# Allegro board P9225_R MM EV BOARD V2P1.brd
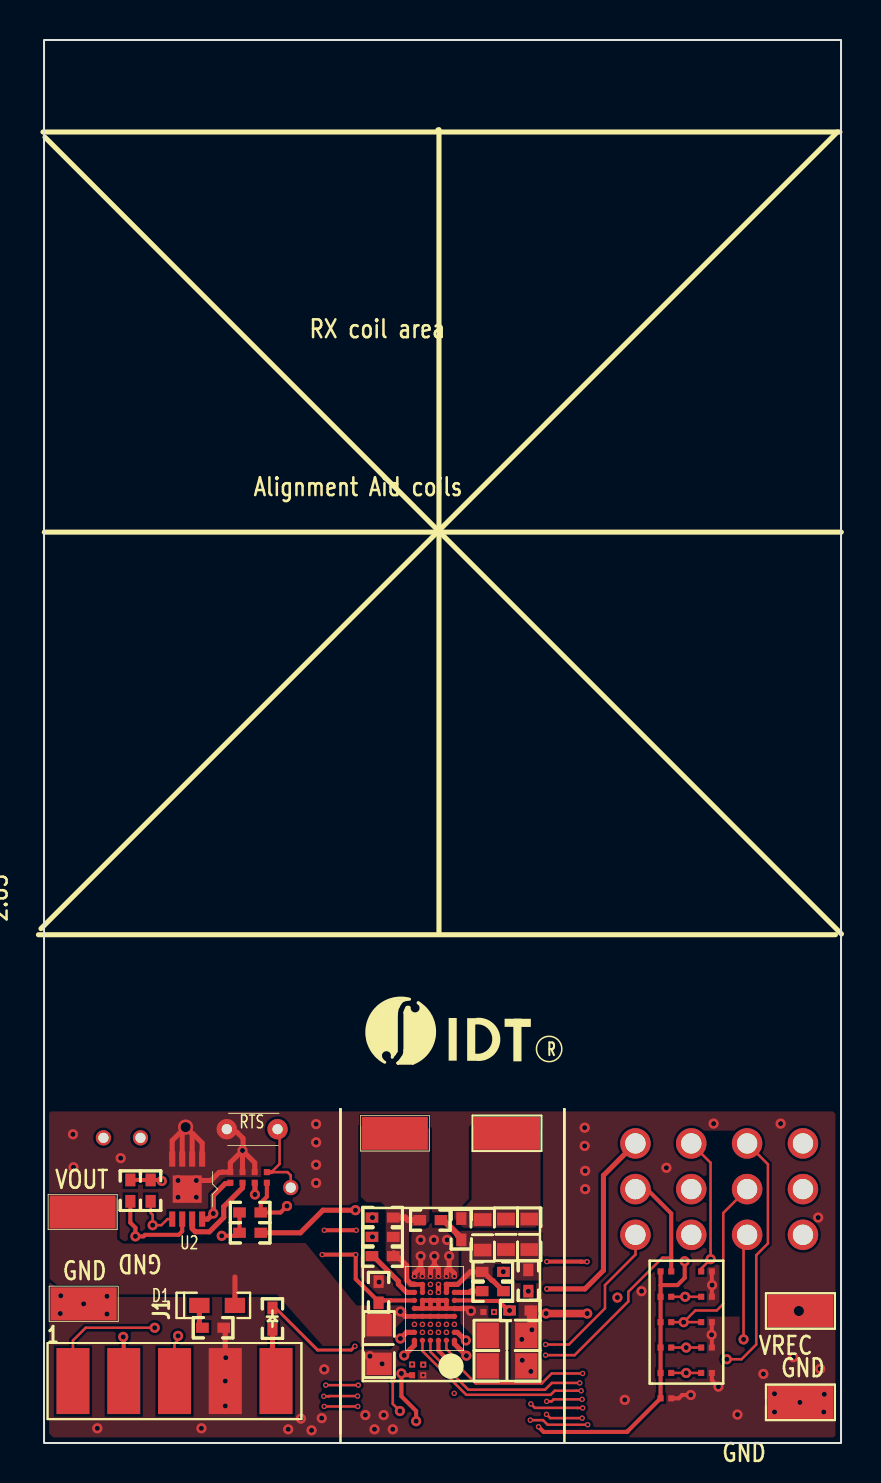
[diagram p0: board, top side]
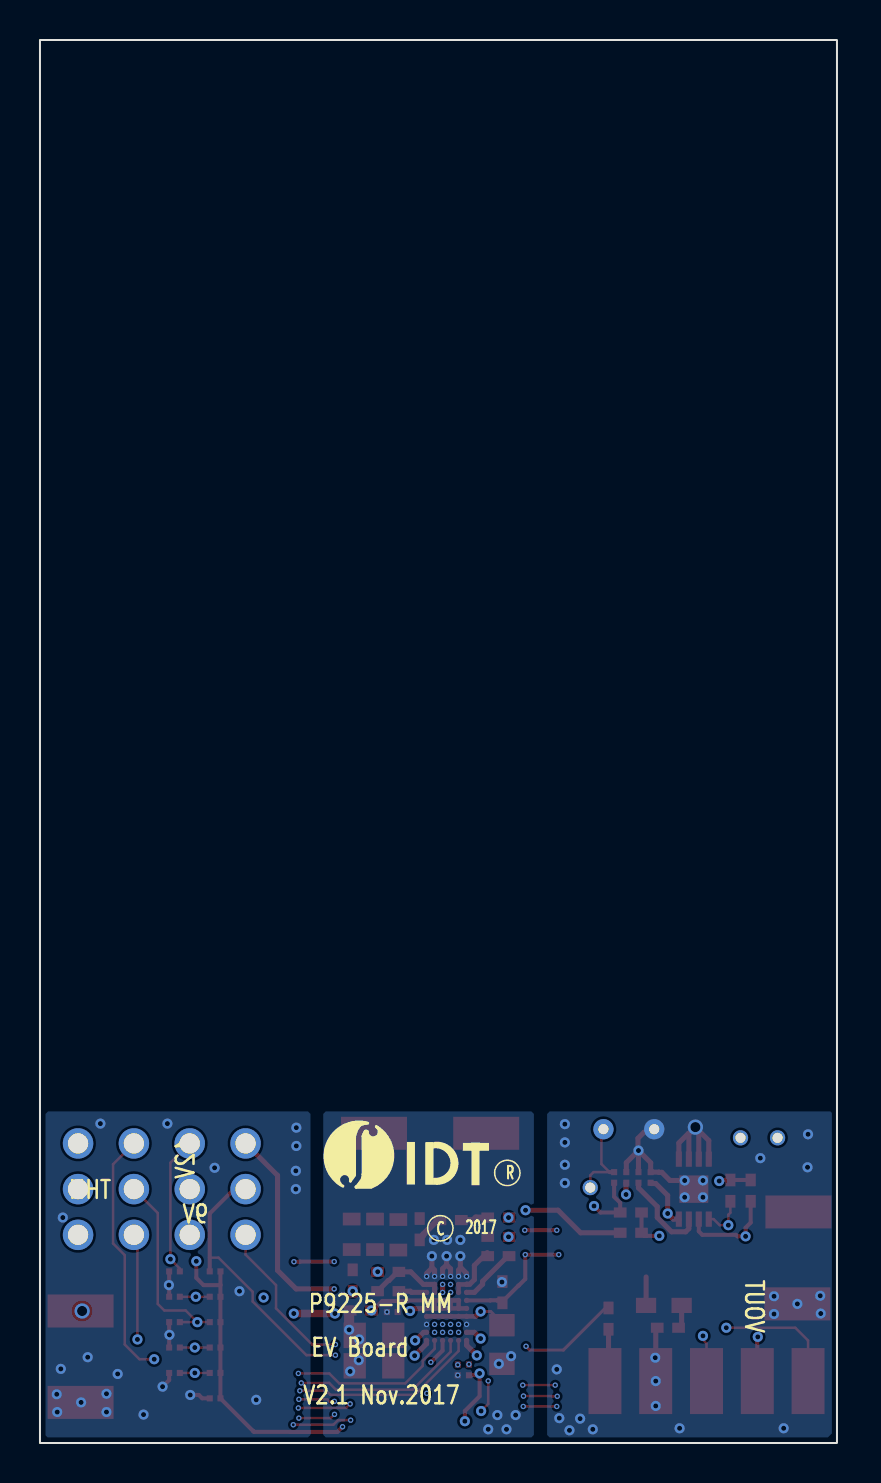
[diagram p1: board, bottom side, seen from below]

Outline 39.88 x 70.18 mm; copper layers: TOP, LAYER_2, LAYER_3, BOTTOM. Coordinates in mm from the lower left corner of the outline.
Outline path: rectangle 0,0 39.88,70.18

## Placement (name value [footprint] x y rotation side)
AC2  NP  [TEST_PT_SM_135X70]  17.55 15.49 0 top
C1  220nF/50V  [0603]  24.28 10.44 90 top
C2  220nF/50V  [0603]  21.95 10.41 90 top
C3  220nF/50V  [0603]  23.11 10.44 90 top
C5  47nF/50V  [0402]  20.88 10.69 90 top
C6  47nF  [0402]  24.23 8.13 270 top
C7  47nF  [0402]  22.45 8.56 0 top
C8  15nF  [0402]  22.45 7.59 180 top
C9  3.3nF  [0402]  19.33 11.15 180 top
C10  22uF  [0805]  16.76 4.93 270 top
C14  47nF  [0402]  16.94 10.31 180 top
C15  47nF  [0402]  16.94 11.28 180 top
C16  15nF  [0402]  16.94 9.35 180 top
C18  1uF  [0402]  23.83 6.63 0 top
C19  0.1uF  [0201]  31.11 2.24 0 top
C20  1uF  [0402]  16.74 7.54 90 top
C21  22uF  [0805]  23.16 5.38 0 top
C22  22uF  [0805]  23.16 3.86 0 top
C23  0.1uF  [0201]  22.25 6.55 0 top
C25  0.1uF  [0201]  9.32 13.28 90 top
C31  0.1uF  [0201]  10.54 13.28 90 top
D1  LED  [0603_DIODE]  8.66 6.88 180 top
D8  1N4148W  [0402]  11.43 6.22 90 top
EOC  PTH_TP  [40MIL_60PAD]  32.38 14.99 0 top
GND  Test Point  [TEST_PT_SM_135X70]  37.85 2.03 0 top
GND1  Test Point  [TEST_PT_SM_135X70]  1.98 6.96 0 top
ILIM  PTH_TP  [40MIL_60PAD]  37.97 10.41 0 top
INT  PTH_TP  [40MIL_60PAD]  29.59 12.7 0 top
J1  I2C  [HEADER_1X5_0P1PITCH60P42D]  6.53 3.1 90 top
LC  NP  [TEST_PT_SM_135X70]  23.16 15.49 0 top
NOREF  -  []  24.82 3.1 90 top
NOREF#2  -  []  26.03 1.15 0 top
NOREF#3  -  []  0 0 0 top
NOREF#4  -  []  0 0 90 top
NOREF#5  -  []  -80.72 -189.41 0 top
NOREF#6  -  []  26.64 0.25 0 top
NOREF#7  -  []  14.83 0.8 0 top
NOREF#8  -  []  0 0 0 top
NOREF#9  -  []  19.15 11.81 0 top
NOREF#10  -  []  26.04 0.05 0 top
NOREF#11  -  []  15.95 3.1 0 top
NOREF#12  -  []  0 0 90 top
NOREF#13  -  []  16.32 13.82 180 bottom
R1  5.1k  [0402]  8.46 5.77 180 top
R6  NP  [0402]  10.31 10.52 0 top
R8  0  [0402]  10.31 11.53 0 top
R13  5.1k  [0402]  4.32 12.62 90 top
R14  5.1k  [0402]  5.33 12.62 90 top
R17  10k  [0201]  18.97 3.66 270 top
R18  10k  [0201]  9.93 13.28 270 top
R19  10k  [0201]  11.15 13.28 90 top
R22  10k  [0201]  33.15 4.78 180 top
R23  10k  [0201]  31.11 8.59 180 top
R27  10k  [0201]  33.15 6.05 180 top
R28  10k  [0201]  31.11 6.05 180 top
R29  10k  [0201]  33.15 3.51 180 top
R30  10k  [0201]  31.11 3.51 180 top
R33  10k  [0201]  33.15 7.32 180 top
R34  NP  [0201]  31.11 7.32 0 top
R38  NP  [0201]  31.11 4.78 180 top
R39  10k  [0201]  18.41 3.66 270 top
R40  10k  [0201]  33.15 8.59 180 top
RPG  PTH_TP  [40MIL_60PAD]  35.18 12.7 0 top
RPO  PTH_TP  [40MIL_60PAD]  32.38 12.7 270 top
RSV0  PTH_TP  [40MIL_60PAD]  29.59 10.41 0 top
RSV1  PTH_TP  [40MIL_60PAD]  32.38 10.41 270 top
RSV4  PTH_TP  [40MIL_60PAD]  35.18 10.41 0 top
RTS  NP  [NTC2]  10.41 15.7 180 top
SCL  PTH_TP  [10MIL_35PAD]  4.83 15.27 0 top
SDA  PTH_TP  [10MIL_35PAD]  2.97 15.27 0 top
TS  PTH_TP  [10MIL_35PAD]  12.34 12.78 0 top
U1  P9225-R0  [CSP52_2P64X3P94_0P4MM]  19.53 6.73 180 top
U2  EEPROM  [TDFN08]  7.16 12.7 270 top
UNK/EN  PTH_TP  [40MIL_60PAD]  35.18 14.99 0 top
VDD5V  PTH_TP  [40MIL_60PAD]  29.59 14.99 0 top
VOSET  PTH_TP  [40MIL_60PAD]  37.97 12.7 0 top
VOUT  Test Point  [TEST_PT_SM_135X70]  1.93 11.56 180 top
VPP18  PTH_TP  [40MIL_60PAD]  37.97 14.99 0 top
VRECT  Test Point  [TEST_PT_SM_135X70]  37.85 6.6 0 top

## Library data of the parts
AC2 EOC GND GND1 ILIM INT LC RPG RPO RSV0 RSV1 RSV4 SCL SDA TS UNK/EN VDD5V VOSET VOUT VPP18 VRECT = PTH_TP
C1-C3 C5-C10 C14-C16 C18-C23 C25 C31 = CAP NP
D1 = LED_0
D8 = DIODE_0
J1 = CON5
R1 R6 R8 R13 R14 R17-R19 R22 R23 R27-R30 R33 R34 R38-R40 = RESISTOR
RTS = RESISTOR_0
U1 = IDTP9220_CSP_13
U2 = 24LC128_0

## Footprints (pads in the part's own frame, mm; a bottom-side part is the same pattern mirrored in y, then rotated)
10MIL_35PAD
  round 0.762 hole 0.508: 1(0,0)
40MIL_60PAD
  round 1.524 hole 1.016: 1(0,0)
0201
  rect 0.305x0.305 smd: 1(-0.267,0) 2(0.267,0)
0402
  rect 0.635x0.508 smd: 1(-0.533,0) 2(0.533,0)
0603
  rect 0.635x0.889 smd: 1(-0.762,0) 2(0.762,0)
0603_DIODE
  rect 1.016x0.762 smd: 1(-0.889,0) 2(0.889,0)
0805
  rect 1.118x1.27 smd: 1(-0.965,0) 2(0.965,0)
CSP52_2P64X3P94_0P4MM
  round 0.269 smd: A1(-1.001,1.6) A2(-0.599,1.6) A3(-0.201,1.6) A4(0.201,1.6) A5(0.599,1.6) A6(1.001,1.6) B1(-1.001,1.199) B2(-0.599,1.199) B3(-0.201,1.199) B4(0.201,1.199) B5(0.599,1.199) B6(1.001,1.199) C1(-1.001,0.8) C2(-0.599,0.8) C3(-0.201,0.8) C4(0.201,0.8) C5(0.599,0.8) C6(1.001,0.8) D1(-1.001,0.399) D2(-0.599,0.399) D3(-0.201,0.399) D4(0.201,0.399) D5(0.599,0.399) D6(1.001,0.399) E1(-1.001,0) E2(-0.599,0) E5(0.599,0) E6(1.001,0) F1(-1.001,-0.399) F2(-0.599,-0.399) F3(-0.201,-0.399) F4(0.201,-0.399) F5(0.599,-0.399) F6(1.001,-0.399) G1(-1.001,-0.8) G2(-0.599,-0.8) G3(-0.201,-0.8) G4(0.201,-0.8) G5(0.599,-0.8) G6(1.001,-0.8) H1(-1.001,-1.199) H2(-0.599,-1.199) H3(-0.201,-1.199) H4(0.201,-1.199) H5(0.599,-1.199) H6(1.001,-1.199) J1(-1.001,-1.6) J2(-0.599,-1.6) J3(-0.201,-1.6) J4(0.201,-1.6) J5(0.599,-1.6) J6(1.001,-1.6)
HEADER_1X5_0P1PITCH60P42D
  rect 3.302x1.651 smd: 1(0,5.08) 2(0,2.54) 3(0,0) 4(0,-2.54) 5(0,-5.08)
NTC2
  round 1.016 hole 0.508: 1(-1.27,0) 2(1.27,0)
TDFN08
  rect 0.762x0.305 smd: 1(-1.501,0.749) 2(-1.501,0.249) 3(-1.501,-0.249) 4(-1.501,-0.749) 5(1.501,-0.749) 6(1.501,-0.249) 7(1.501,0.249) 8(1.501,0.749)
  rect 1.372x1.448 smd: 9(0,0)
TEST_PT_SM_135X70
  rect 3.302x1.651 smd: 1(0,0)

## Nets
GND_POWER: C10.2 C18.2 C19.2 C20.2 C21.2 C22.2 C23.2 C25.2 C31.2 GND.1 GND1.1 J1.4 R1.1 R17.2 R18.1 R22.1 R27.1 R29.1 R33.1 R40.1 RTS.2 U1.C1(GND) U1.C6(GND1) U1.J1(GND2) U1.J2(GND3) U1.J3(GND4) U1.J4(GND5) U1.J5(GND6) U1.J6(GND7) U2.1(A0) U2.2(A1) U2.3(A2) U2.4(VSS) U2.9(E_PAD)
VDD5V: C18.1 R6.2 U1.F1(VDD5V) VDD5V.1
INT: INT.1 J1.1 R23.1 U1.C3(I\N\T\)
OD3: EOC.1 R40.2 U1.A2(EOC)
OD4: RSV0.1 U1.B2(RSV0)
THM: C31.1 R19.2 RTS.1 TS.1 U1.H4(TS)
VOUT: C10.1 D1.1(ANODE) U1.D1(OUT) U1.D2(OUT1) U1.D3(OUT2) U1.D4(OUT3) U1.D5(OUT4) U1.D6(OUT5) U1.G3(RSV3) U1.H3(RSV2) VOUT.1
VPP18: C19.1 C20.1 R8.2 R19.1 R23.2 R28.2 R30.2 R34.1 R38.2 R39.2 U1.F6(VDD18) VPP18.1
VRECT: C21.1 C22.1 C23.1 D8.2(K) U1.C2(SINK) U1.E1(VRECT) U1.E2(VRECT1) U1.E5(VRECT2) U1.E6(VRECT3) U1.F2(VRECT4) U1.F3(VRECT5) U1.F4(VRECT6) U1.F5(VRECT7) VRECT.1
WP: R18.2 U2.7(WP)
N7563167: R17.1 U1.B5(E\N\) UNK/EN.1
N7563825: C15.2 U1.B6(COMB)
N7563835: C14.2 U1.A6(COM2)
N7563843: AC2.1 C9.2 C14.1 C15.1 C16.1 U1.G5(AC2) U1.H5(AC2_1) U1.H6(AC2_2)
N7563887: C8.2 U1.G1(BST1)
N7563891: C6.2 U1.A1(COM1)
N7563895: C1.1 C2.1 C3.1 C5.1 C6.1 C7.1 C8.1 C9.1 U1.G2(AC1) U1.H1(AC1_1) U1.H2(AC1_2)
N7564147: C1.2 C2.2 C3.2 C5.2 LC.1
N7564207: C7.2 U1.B1(COMA)
N7564297: C25.1 R6.1 R8.1 R13.2 R14.2 U2.8(VCC)
N7564401: R27.2 R28.1 RPG.1 U1.A5(RPPG)
N7564413: ILIM.1 R22.2 R38.1 U1.B4(ILIM)
N7564491: J1.2 R13.1 SCL.1 U1.A3(SCL) U2.6(SCL)
N7564497: J1.3 R14.1 SDA.1 U1.B3(SDA) U2.5(SDA)
N7564631: R33.2 R34.2 U1.A4(VOSET) VOSET.1
N7566649: R39.1 RSV4.1 U1.C5(RSV4)
N7566662: R29.2 R30.1 RPO.1 U1.C4(RPPO)
N8120855: C16.2 U1.G6(BST2)
N8141222: D1.2(CATHODE) R1.2
N16756161: D8.1(A) J1.5
N16788637: RSV1.1 U1.G4(RSV1)

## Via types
v1: diameter 0.269, hole 0.152, TOP to BOTTOM, 55 vias
v2: diameter 0.508, hole 0.254, TOP to BOTTOM, 103 vias
v3: diameter 0.762, hole 0.508, TOP to BOTTOM, 2 vias

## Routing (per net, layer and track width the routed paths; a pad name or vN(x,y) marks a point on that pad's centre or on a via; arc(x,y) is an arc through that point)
GND_POWER: length 27.1
  TOP w0.203: R33.1 33.41,7.89 v2(33.43,7.9) 33.41,7.91 R40.1 ; R27.1 33.41,5.42 v2(33.4,5.41) 33.41,5.4 R22.1 ; C19.2 31.76,2.24 31.93,2.4 v2(32.36,2.4) ; R29.1 33.41,3.15 v2(33.74,2.82)
  TOP w0.254: 6.91,15.63 6.41,15.13 U2.4 ; 6.91,15.63 U2.3 ; 6.91,15.63 v3(7.08,15.8) 7.38,15.5 7.41,15.47 ; 19.53,8.92 19.73,8.71 v1(19.73,8.33) ; 19.53,8.92 v2(19.53,9.35) ; 19.53,8.92 19.33,8.72 v1(19.33,8.33) ; R1.1 9.07,5.69 v2(9.07,3.1) 9.04,3.12 ; 20.27,8.78 20.27,8.72 20.29,8.72 20.52,8.5 20.52,8.35 v1(20.53,8.33) ; 20.27,8.78 20.13,8.65 v1(20.13,8.33) ; 20.27,8.78 v2(20.27,9.35) ; v2(9.93,14.63) 9.32,14.02 C25.2 8.92,13.55 8.9,13.54 8.76,13.54 8.36,13.13 v2(7.62,13.13) ; v2(9.93,14.63) 10.54,14.02 C31.2 ; v2(9.93,14.63) R18.1 ; v2(9.93,14.63) 9.96,14.66 9.96,15.24 9.65,15.54 9.3,15.54 RTS.2 ; 18.93,9.26 v2(18.85,9.35) 18.85,8.74 ; 18.85,8.74 18.85,8.72 18.77,8.72 18.54,8.5 18.54,8.34 v1(18.53,8.33) ; 18.85,8.74 18.93,8.65 v1(18.93,8.33) ; 7.41,15.47 7.45,15.47 7.91,15.01 U2.1 ; 7.41,15.47 U2.2
  TOP w0.508: C18.2 24.41,6.58 v2(24.41,5.66)
  vias: v1(18.53,5.93) v1(18.97,3.39) v1(20.53,5.93) v1(22.52,6.55) v2(0.84,7.37) v2(0.81,6.48) v2(1.45,15.44) v2(1.47,13.79) v2(1.98,6.96) v2(2.67,0.74) v2(3.15,7.34) v2(3.15,6.45) v2(3.84,14.25) v2(6.71,13.13) v2(6.71,12.29) v2(7.62,12.29) v2(7.87,0.74) v2(9.09,4.27) v2(9.07,1.85) v2(12.22,0.69) v2(12.85,1.22) v2(13.39,0.64) v2(13.61,15.95) v2(13.61,15.04) v2(13.61,13.92) v2(13.61,13) v2(13.89,1.24) v2(14.02,3.68) v2(16.08,1.4) v2(16.31,4.34) v2(16.54,0.69) v2(16.76,8.05) v2(16.92,3.96) v2(16.99,1.4) v2(17.45,0.69) v2(18.85,10.16) v2(19.51,10.16) v2(20.17,10.16) v2(23.91,5.18) v2(23.93,4.14) v2(24.36,3.58) v2(27.05,15.77) v2(27.05,14.86) v2(27.08,13.61) v2(27.08,12.7) v2(29.06,2.16) v2(29.9,7.59) v2(31.14,13.77) v2(33.5,15.98) v2(34.7,1.42) v2(35.99,3.45) v2(36.55,2.46) v2(36.55,1.55) v2(36.86,15.98) v2(37.49,4.29) v2(37.82,2.03) v2(38.73,11.28) v2(38.84,3.71) v2(39.04,2.44) v2(39.01,1.55)
VDD5V: length 33.4
  TOP w0.203: v2(23.29,6.63) 23.23,6.63 22.75,7.11 21.51,7.11 21.48,7.13 U1.F1
  TOP w0.254: v1(25.16,7.71) 27.06,7.71 27.99,8.64 27.99,13.39 VDD5V.1 ; v2(15.58,11.65) 13.96,11.65 12.83,10.52 R6.2
  LAYER_2 w0.203: v1(25.16,7.71) 25.18,7.71 24.51,7.04 23.7,7.04 v2(23.29,6.63)
  LAYER_3 w0.254: v2(15.58,11.65) 16.05,12.12 22.45,12.12 24.41,10.16 24.41,8.46 v1(25.16,7.71)
INT: length 46
  TOP w0.127: v2(5.54,5.77) 2.08,5.77 1.45,5.13 J1.1 ; 31.38,9.27 30.94,9.27 29.24,7.56 29.24,7.08 26.55,4.39 v1(25.1,4.39) ; v1(14,2.34) 14.24,2.34 14.25,2.35 v1(15.69,2.35)
  TOP w0.203: INT.1 30.17,12.7 31.38,11.48 R23.1
  LAYER_2 w0.127: v2(5.54,5.77) 5.8,6.03 9.28,6.03 12.97,2.34 v1(14,2.34) ; v1(15.69,2.35) 19.8,2.35 22.07,4.62 22.47,4.62 ; v1(19.73,5.93) 20.1,6.3 20.79,6.3 22.47,4.62 ; 22.47,4.62 24.87,4.62 v1(25.1,4.39)
OD3: length 24.1
  TOP w0.127: v1(26.95,3.48) 25.4,3.48 24.9,2.98 21.6,2.98 20.73,3.86 20.73,4.11 20.13,4.71 U1.A2 ; R40.2 32.88,8.72 v2(33.35,9.2) 33.35,9.57 33.35,9.57 33.35,14.02 EOC.1
  LAYER_3 w0.127: v1(26.95,3.48) 31.04,7.57 31.35,7.57 32.98,9.2 v2(33.35,9.2)
OD4: length 14.5
  TOP w0.127: v1(25.1,4.93) 26.26,4.93 28.07,6.74 28.07,7.9 29.59,9.42 RSV0.1
  LAYER_3 w0.127: v1(25.1,4.93) 24.79,4.62 23.57,4.62 22.87,3.92 20.95,3.92 20.13,4.74 v1(20.13,5.53)
THM: length 16.3
  TOP w0.127: TS.1 12.34,13.39 12.18,13.55 11.38,13.55 11.79,13.96 11.79,15.6 RTS.1
  TOP w0.203: v1(15.62,10.64) v1(14.02,10.64) ; 11.38,13.55 R19.2
  TOP w0.254: v2(10.55,12.43) 10.55,13 C31.1
  LAYER_2 w0.203: v1(15.62,10.64) 15.62,10.19 17.87,7.93 v1(19.33,7.93) ; v1(14.02,10.64) 14.02,11.1 TS.1 10.9,12.78 v2(10.55,12.43)
VOUT: length 8.5
  TOP w0.152: v2(17.83,6.58) 17.32,6.58 16.71,5.97
  TOP w0.229: 18.11,6.33 U1.D6 U1.D5 U1.D4 U1.D3 U1.D2 U1.D1
  TOP w0.254: v2(17.83,6.58) 18.07,6.33 18.11,6.33 ; D1.1 9.55,8.31 ; v1(19.73,7.93) v1(19.73,7.53)
  LAYER_3 w0.203: v2(17.83,6.58) 18.12,6.87 19.36,6.87 19.73,7.24 v1(19.73,7.53)
VPP18: length 55.3
  TOP w0.203: v1(13.92,9.42) v1(15.6,9.42) 15.6,8.2 15.93,7.87 15.94,7.87 16.74,7.07 C20.1 16.86,7.13 17.01,7.13 17.02,7.14 17.34,7.14 17.35,7.13 U1.F6 ; 30.85,7.9 R34.1 R28.2 R38.2 R30.2 C19.1 29.22,0.61 29.22,0.61 29.2,0.59 29.19,0.59 29.16,0.56 27.36,0.56 27.36,0.55 25,0.55 v1(24.74,0.81) ; 30.85,7.9 R23.2 ; 30.85,7.9 31.7,7.9 32.05,8.26 v2(32.05,9.09) ; R39.2 17.97,3.39 v2(17.88,3.48) 17.88,2.34 18.62,1.6 v2(18.62,1.09) ; R19.1 11.15,12.32 10.85,12.01 R8.2 11.83,11.53 v2(12.16,11.85)
  LAYER_2 w0.203: v2(18.62,1.09) 23.52,1.09 23.8,0.81 v1(24.74,0.81) ; v2(32.05,9.09) 32.51,9.09 33.69,10.27 33.69,12.88 34.67,13.86 36.85,13.86 VPP18.1
  LAYER_3 w0.203: v2(12.16,11.85) 12.16,11.19 v1(13.92,9.42) ; v2(17.88,3.48) 16.64,3.48 16.38,3.48 15.93,3.94 15.83,4.04 15.83,4.14 15.82,4.14 15.82,4.67 15.86,4.71 15.86,4.96 15.85,4.98 15.85,5.11 15.6,5.36 v1(15.6,9.42)
VRECT: length 39.1
  TOP w0.152: v1(15.56,4.84) 15.37,4.65 13.69,4.65 11.58,6.76 D8.2
  TOP w0.229: U1.E6 U1.E5 ; U1.E5 19.35,6.73 ; U1.E5 U1.F5 U1.F4 ; 19.35,6.73 19.33,6.76 19.33,7.13 U1.F3 ; 19.35,6.73 19.75,6.73 ; U1.F3 19.73,6.75 19.75,6.73 ; U1.F3 U1.F2 20.13,7.13 20.13,6.73 U1.E1 ; 19.75,6.73 U1.E2
  TOP w0.254: U1.E2 20.13,6.73 ; v2(21.36,6.6) 21.35,6.6 21.23,6.72 20.54,6.72 U1.E1 ; 19.33,7.13 U1.F4
  TOP w0.381: v2(27.18,6.48) v2(25.12,6.48)
  LAYER_2 w0.152: v1(15.56,4.84) 15.82,5.11 15.82,6.43 16.48,7.09 18.16,7.09 18.52,6.73 21.18,6.73 21.31,6.6 v2(21.36,6.6)
  LAYER_2 w0.381: v2(21.36,6.6) 21.95,6.02 23.75,6.02 24.21,6.48 v2(25.12,6.48) ; v3(37.77,6.6) 35.86,8.51 28.39,8.51 27.18,7.29 v2(27.18,6.48)
  LAYER_3 w0.254: v1(20.13,5.93) 20.13,6.25 20.49,6.6 v2(21.36,6.6)
WP: length 4.5
  TOP w0.254: U2.7 7.41,10.72 7.57,10.56 8.27,10.56 8.99,11.28 8.99,11.82 9.93,12.76 R18.2
N7563167: length 32.5
  TOP w0.127: v1(26.92,1.24) 25.33,1.24 v1(25.14,1.43) ; UNK/EN.1 36.22,13.94 36.22,9.98 35.64,9.4 35.64,4.93 34.9,4.19 v2(34.16,4.19)
  LAYER_3 w0.127: v1(26.92,1.24) 29.87,4.19 v2(34.16,4.19) ; v1(25.14,1.43) 25.14,1.45 25.12,1.45 25.12,1.4 25.02,1.5 24.18,1.5 23.96,1.71 19.95,1.71 19.33,2.34 19.33,3.56 v1(18.97,3.91) 18.97,4.21 18.93,4.25 v1(18.93,5.53)
N7563825: length 7.7
  TOP w0.254: U1.B6 18.14,5.53 v2(17.83,5.22)
  LAYER_3 w0.508: v2(17.83,5.22) 17.2,5.86 17.2,7.44 17.45,7.7 17.45,10.26 v2(16.43,11.28)
N7563835: length 8.1
  TOP w0.254: v2(18.02,4.38) 18.33,4.69 18.33,4.69 18.53,4.89 U1.A6
  LAYER_3 w0.508: v2(16.43,10.31) 16.43,9.75 16.13,9.45 16.13,5.81 17.56,4.38 v2(18.02,4.38)
N7563843: length 4.3
  TOP w0.229: U1.H6 U1.H5 U1.G5
  TOP w0.254: 17.5,9.53 18.14,8.88 18.14,8.17 18.37,7.95 18.52,7.95 U1.H6
  TOP w0.305: C9.2 18.2,11.15 18.07,11.28 C15.1
N7563887: length 1.4
  TOP w0.254: U1.G1 21.29,7.53 21.35,7.59 C8.2
N7563891: length 6.1
  TOP w0.254: U1.A1 20.53,4.97 20.82,4.68 20.83,4.68 v2(21.13,4.37)
  LAYER_3 w0.508: v2(21.13,4.37) 22.15,4.37 23.84,6.06 23.84,7.2 v2(24.23,7.59)
N7563895: length 5.4
  TOP w0.254: U1.G2 20.13,7.54 20.13,7.93 ; 20.13,7.93 U1.H1 20.7,7.93 21.32,8.56 C7.1 21.98,8.56 22.42,8.13 22.46,8.13 C8.1 ; 20.13,7.93 U1.H2
  TOP w0.305: C5.1 20.88,10.21 20.7,10.39 20.7,10.43 19.98,11.15 C9.1
N7564207: length 5
  TOP w0.254: v2(21.11,5.13) 21.09,5.13 20.7,5.52 20.68,5.52 20.67,5.53 U1.B1
  LAYER_3 w0.508: v2(22.98,8.57) 22,7.58 22,6.02 v2(21.11,5.13)
N7564297: length 11.4
  TOP w0.203: 5.77,13.16 R14.2 R13.2 ; v2(8.89,10.36) 9.63,10.36 R6.1 R8.1
  TOP w0.254: v2(5.89,13.11) 5.82,13.11 5.77,13.16 ; U2.8 8.19,11.2 v2(8.47,11.48) 8.47,12.38 9.07,12.98 9.28,12.98 C25.1
  LAYER_2 w0.203: v2(8.89,10.36) 8.47,10.78 v2(8.47,11.48)
  LAYER_3 w0.254: v2(5.89,13.11) 5.89,12.09 6.5,11.48 v2(8.47,11.48)
N7564401: length 26.1
  TOP w0.127: RPG.1 33.99,11.51 33.99,6.96 33.66,6.63 32.59,6.63 v2(32,6.05) ; U1.A5 18.93,4.6 21.12,2.41 25.35,2.41 25.55,2.62 26.62,2.62 26.63,2.61 v1(26.88,2.61) ; R28.1 v2(32,6.05) ; v2(32,6.05) R27.2
  LAYER_3 w0.127: v1(26.88,2.61) 27.12,2.61 29.94,5.43 31.39,5.43 v2(32,6.05)
N7564413: length 27.6
  TOP w0.127: v1(25.15,2.08) 25.39,2.08 25.5,2.18 v1(26.92,2.18) ; R38.1 v2(32.13,4.78) R22.2
  LAYER_3 w0.127: v1(26.92,2.18) 27.25,2.18 29.84,4.78 v2(32.13,4.78) 33.71,4.78 37.97,9.04 ILIM.1 ; v1(25.15,2.08) 24.97,2.26 21.11,2.26 20.85,2.01 20.24,2.01 19.63,2.62 19.63,4.11 19.33,4.41 v1(19.33,5.53)
N7564491: length 37.7
  TOP w0.127: v1(15.72,2.9) v1(14.1,2.9)
  TOP w0.203: v2(3.96,5.31) 3.99,5.28 J1.2 ; R13.1 4.32,11.02 4.57,10.77 v2(4.57,10.34) 4.98,10.34 5.05,10.41 6.74,10.41 6.91,10.59 U2.6 ; U1.A3 19.73,4.63 v1(20.32,4.04)
  LAYER_2 w0.127: v1(20.32,4.04) 19.03,2.75 15.87,2.75 v1(15.72,2.9) ; v1(14.1,2.9) 13.21,2.9 9.63,6.47 5.13,6.47 v2(3.96,5.31)
  LAYER_2 w0.203: SCL.1 4.83,10.59 v2(4.57,10.34)
  LAYER_3 w0.127: v2(3.96,5.31) 4.57,5.92 v2(4.57,10.34)
N7564497: length 35.2
  TOP w0.127: J1.3 6.53,4.98 6.71,5.16 v2(6.71,5.36) ; v1(15.7,1.83) v1(14.02,1.83) ; U2.5 6.17,11.2 5.87,10.9 v2(5.44,10.9) 5.44,11.42 5.33,11.52 R14.1
  LAYER_2 w0.127: v1(20.52,2.48) 20.1,2.06 15.93,2.06 v1(15.7,1.83) ; v2(6.71,5.36) 9.12,5.36 12.65,1.83 v1(14.02,1.83)
  LAYER_3 w0.127: SDA.1 3,15.24 3,13.34 v2(5.44,10.9) 5.44,6.63 v2(6.71,5.36) ; v1(19.73,5.53) 19.73,4.57 19.99,4.32 19.99,2.77 20.27,2.48 v1(20.52,2.48)
N7564631: length 26.7
  TOP w0.127: v1(26.8,3) 25.41,3 25.07,2.67 21.23,2.67 19.33,4.56 U1.A4 ; R33.2 v2(32.08,7.32) R34.2
  LAYER_3 w0.127: v1(26.8,3) 27.05,3 31.36,7.32 v2(32.08,7.32) 34.34,7.32 36.47,9.45 36.47,11.2 VOSET.1
N7566649: length 30.5
  TOP w0.127: v1(27.2,0.91) 25.2,0.91 24.97,1.14 v1(24.33,1.14) ; RSV4.1 35.18,9.84 35,9.66 v2(35,5.18)
  LAYER_3 w0.127: v1(24.33,1.14) 19.89,1.14 19.75,1.28 ; v1(27.2,0.91) 32.56,0.91 35,3.35 v2(35,5.18)
  LAYER_3 w0.152: v1(18.93,5.93) 18.93,6.15 18.78,6.3 18.21,6.3 18.09,6.18 18.05,6.13 18.05,5.77 18.59,5.23 18.59,4.11 v1(18.41,3.94) 18.41,2.62 19.75,1.28
N7566662: length 34.3
  TOP w0.127: R29.2 v2(32.13,3.51) R30.1 ; v1(17.45,3.11) 17.45,1.96 v2(17.81,1.6) ; v1(26.95,1.75) 26.7,1.75 26.7,1.76 24.56,1.76 v1(24.36,1.96)
  LAYER_2 w0.127: v2(17.81,1.6) 24,1.6 v1(24.36,1.96) ; v2(32.13,3.51) 28.88,3.51 ; 28.88,3.51 28.88,3.43 27.2,1.75 v1(26.95,1.75) ; 28.88,3.51 28.69,3.7 v2(28.69,7.28) ; v1(19.33,5.93) 19.33,6.05 19.03,6.35 18.07,6.35 17.97,6.25 17.96,6.25 17.4,5.69 17.4,3.43 17.45,3.38 v1(17.45,3.11)
  LAYER_3 w0.127: v2(28.69,7.28) 31.29,9.88 31.29,10.74 32.38,11.84 RPO.1
N8120855: length 3
  TOP w0.254: U1.G6 18.14,7.53 17.73,7.95 17.73,8.09 16.47,9.35 C16.2
N8141222: length 1.2
  TOP w0.254: D1.2 7.77,5.92 R1.2
N16756161: length 2.7
  TOP w0.254: D8.1 11.43,3.28 J1.5
N16788637: length 14.6
  TOP w0.203: v1(27.17,9.07) 26.88,9.07 26.87,9.08 v1(25.16,9.08)
  LAYER_2 w0.203: v1(19.33,7.53) 19.43,7.44 19.43,7.41 19.75,7.09 21.56,7.09 21.57,7.08 22.8,7.08 24.79,9.08 v1(25.16,9.08) ; RSV1.1 31.04,9.07 v1(27.17,9.07)

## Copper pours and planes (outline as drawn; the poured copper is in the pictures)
GND_POWER on TOP: 18.39,10.36 18.39,8.47 18.55,8.32 20.44,8.32 20.57,8.45 20.57,10.19 20.27,10.49 18.52,10.49
GND_POWER on TOP: 0.33,16.59 0.25,16.51 0.25,0.48 0.46,0.28 39.5,0.28 39.6,0.38 39.6,16.46 39.47,16.59 ; 8 cut-outs
GND_POWER on BOTTOM: 26.34,0.41 26.47,0.28 39.5,0.28 39.6,0.38 39.6,16.46 39.47,16.59 26.47,16.59 26.34,16.46
GND_POWER on BOTTOM: 0.33,16.59 0.25,16.51 0.25,0.48 0.46,0.28 14.38,0.28 14.5,0.41 14.5,16.46 14.38,16.59
GND_POWER on BOTTOM: 15.16,16.46 15.29,16.59 25.58,16.59 25.7,16.46 25.7,0.41 25.58,0.28 15.29,0.28 15.16,0.41
GND_POWER on LAYER_2: 0.25,0.48 0.46,0.28 39.5,0.28 39.6,0.38 39.6,16.46 39.47,16.59 0.33,16.59 0.25,16.51 ; 4 cut-outs
GND_POWER on LAYER_3: 0.25,0.48 0.46,0.28 39.5,0.28 39.6,0.38 39.6,16.46 39.47,16.59 0.33,16.59 0.25,16.51 ; 5 cut-outs
VOUT on TOP: 0.43,12.37 3.4,12.37 3.66,12.24 3.66,10.19 3.94,9.97 13.08,10.01 15.63,6.88 17.93,6.88 18.16,6.65 18.16,6.32 17.53,5.69 17.53,5.05 17.28,4.81 13.99,4.81 11.65,7.43 1.22,7.43 0.28,8.22 0.28,12.19
VRECT on TOP: 20.88,6.91 22.18,6.91 22.27,6.82 22.27,6.36 22.37,6.26 23.04,6.26 23.22,6.07 23.22,3.23 23.14,3.15 21.69,3.15 21.51,3.33 21.51,5.3 20.84,5.97 20.84,6.87
N7563843 on TOP: 15.85,12.32 16.13,12.04 16.87,12.04 17.09,11.81 17.09,9.14 17.65,8.59 17.65,8.13 17.98,7.8 18.57,7.8 18.59,7.82 18.59,8.05 18.54,8.1 18.34,8.1 18.26,8.18 18.26,10.69 18.41,10.85 19.05,10.85 19.28,11.12 19.28,15.69 19.1,15.88 15.9,15.88 15.85,15.82
N7563895 on TOP: 20.87,10.62 24.66,10.62 24.82,10.46 24.82,8.2 24.74,8.13 23.62,8.13 23.52,8.23 23.52,8.94 22.65,8.94 22.45,8.74 22.45,8.2 20.88,8.2 20.88,9.58 20.89,9.61 20.75,9.75 20.75,10.5
N7564147 on TOP: 21.39,12.17 20.93,11.68 20.52,11.68 20.52,11.23 20.98,10.77 24.56,10.77 24.84,11.04 24.84,15.67 24.61,15.88 21.49,15.88 21.39,15.77

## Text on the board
Board Geometry/Soldermask Bottom: 08_SMASK_BOT
Ref Des/Silkscreen Bottom: 06_SILK_BOT | 9V | THM | EV Board | P9225-R MM | V2.1 Nov.2017 | VOUT | 12V
Ref Des/Assembly Top: D1
Board Geometry/Soldermask Top: 07_SMASK_TOP
Package Geometry/Pastemask Top: 09_PASTE_TOP
Ref Des/Silkscreen Top: 1 | J1 | VOUT | GND | Alignment Aid coils | RX coil area | VREC | 2.85" | 1.57"
User.39: V-score line | V_Cut only on bottom layer | Score here so that board can be broken off by customer | 11. 0.005  AND 0.01 INCH HOLES ON COMPONENT SOLDER PADS SHALL BE FILLED WITH NON CONDUCTIVE EPOXY AND THEN | .4 MICRON. EPOXY TO BE PETERS PP2795 OR EQUIVALENT AS APPROVED BY IDT | PLATED OVER PRIOR TO SURFACE FINISH. PAD ROUGHNESS NOT TO EXCEED | (0.0048) THICK | (0.0048)  THICK | LAYER #1 TOP SIDE (2 OZ) | LAYER #2 GND (1 OZ) | LAYER #3 PWR (1 OZ) | LAYER #4 BOTTOM SIDE (2 OZ) | BOTTOM SIDE SOLDERMASK | BOTTOM SIDE SILKSCREEN | TOP SIDE SILKSCREEN | TOP SIDE SOLDERMASK | NOTES: | 10. TOOLING HOLES TO BE DRILLED AT SAME TIME AS ALL OTHER HOLES. | 12. BOARDS MUST BE CERTIFIED TO BE COMPIANT TO ROHS 6 MATERIALS AND | 6. ETCH VENDOR ID, UL DESIGNATION AND DATECODE ON THE BACKSIDE. | 7. SOLDER MASK BOTH SIDES GREEN USING LIQUID PHOTO IMAGEABLE METHOD. | 9. ALL ARTWORK MEDIA SHALL BE SUPPLIED BY IDT. NO CHANGES WILL BE | BUILD IN ACCORDANCE WITH IPC 6011 & IPC 6012. CLASS 2. | LAMINATE MATERIAL SHALL MEET THE REQUIREMENTS OF IPC 4101. | TYPE 370HR PER STACKUP DETAIL, OR EQUIVALENT. | (NOMINAL DIELECTRICS WITHIN 0.8 MILS [20 MICRONS] OF STACKUP DETAIL). | FINISH: ENIG. 3-8 MICRO-INCHES OF GOLD OVER 150-240 MICRO-INCHES OF NICKEL. | HOLE DIAMETERS ARE AFTER PLATING WITH MINIMUM OF .001 PLATING IN HOLE. | SILKSCREEN BOTH SIDES USING EPOXY BASED, WHITE NON-CONDUCTIVE SILKSCREEN. | NOTE: LEGEND SHOULD BE REMOVED FROM ANY CONDUCTIVE SURFACE | UNLESS OTHERWISE SPECIFIED. | COMPATIBLE TO ROHS 6 ASSEMBLY PROCESS. | NOT USED. | ALLOWED WITHOUT SPECIFIC APPROVAL FROM IDT ENGINEERING. | 1. | 2. | 3. | 4. | 5. | 8. | +.002 | - | 0.031 | SCALE = NONE | VIEW A-A
User.42: FIGURE | SIZE | 6.0 | 10.0 | 20.0 | 40.0 | DRILL CHART: TOP to BOTTOM | ALL UNITS ARE IN MILS | TOLERANCE | +1.0/-2.0 | +1.0/-3.0 | +3.0/-3.0 | PLATED | QTY | 55 | 103 | 2 | 5 | 12
